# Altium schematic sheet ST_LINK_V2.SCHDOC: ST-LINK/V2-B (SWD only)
size A4; Date: Not used; ApprovedBy: Not used; CheckedBy: Not used; Author: Not used; CompanyName: STMicroelectronics; DrawnBy: Not used; Engineer: Not used; Organization: Not used; Address1: Not used; Address2: Not used; Address3: Not used; Address4: Not used; Revision: Not used; SheetNumber: 8; SheetTotal: 8
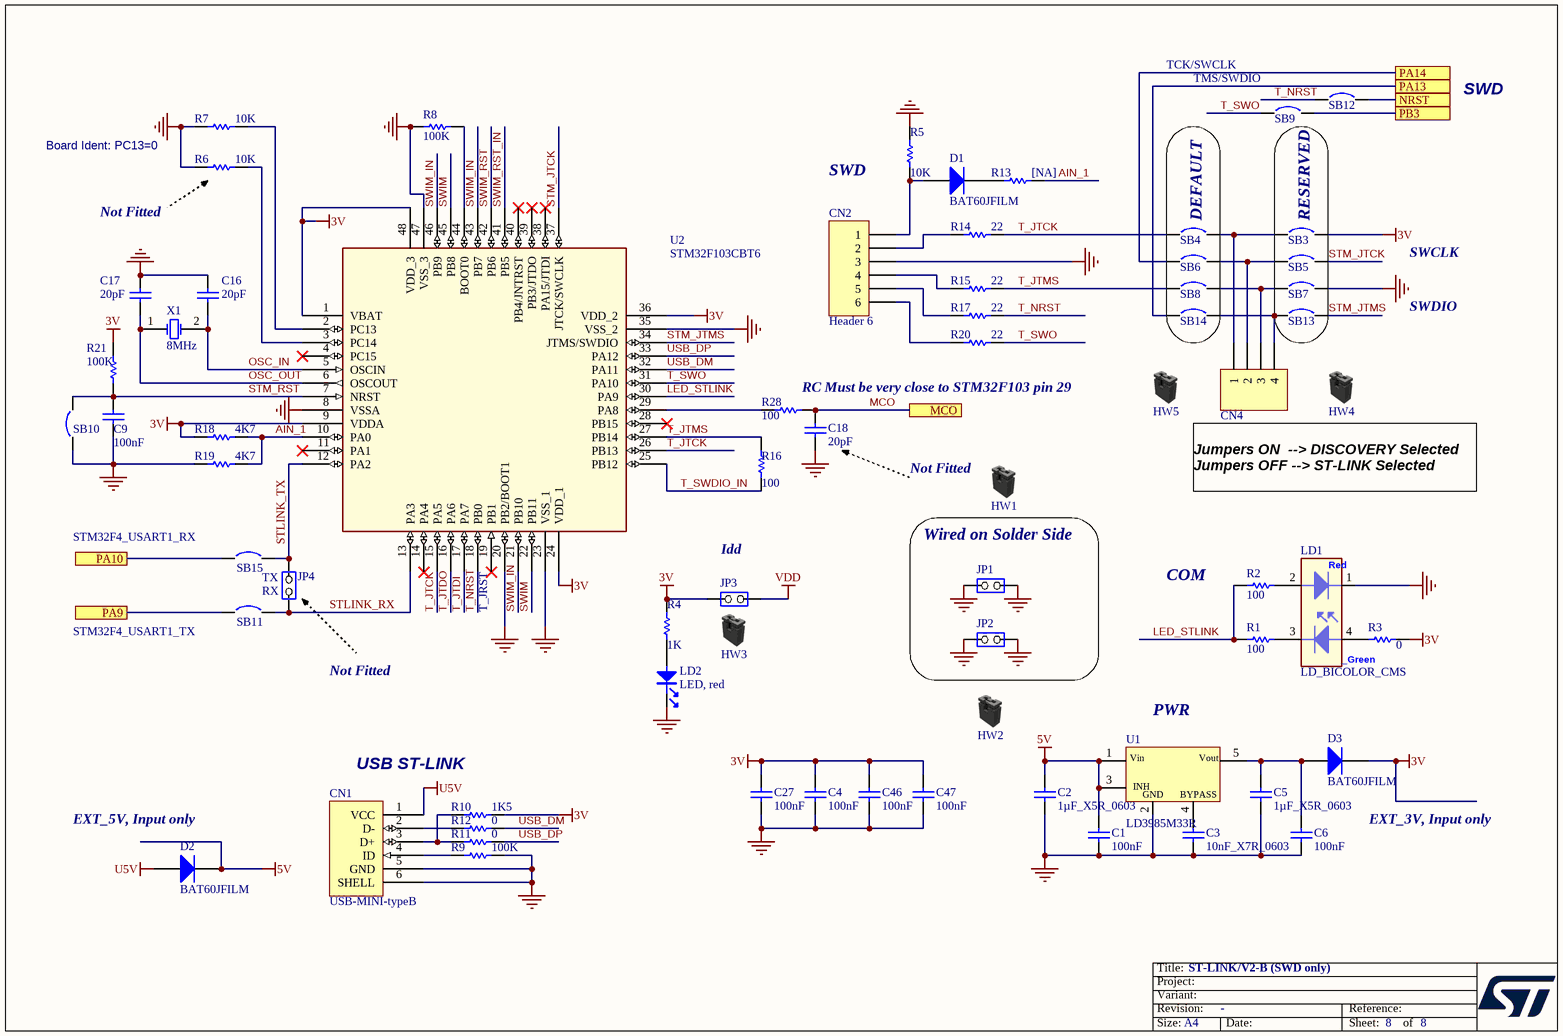
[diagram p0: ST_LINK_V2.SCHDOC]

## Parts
C1  100nF  [0402C]
C2  1µF_X5R_0603  [0603C]
C3  10nF_X7R_0603  [0603C]
C4  100nF  [0402C]
C5  1µF_X5R_0603  [0603C]
C6  100nF  [0402C]
C9  100nF  [0402C]
C16  20pF  [0402C]
C17  20pF  [0402C]
C18  20pF  [0402C]
C27  100nF  [0402C]
C46  100nF  [0402C]
C47  100nF  [0402C]
CN1  USB-MINI-typeB  [USB-MINI-B-SMD]
CN2  Header 6  [HDR1X6]
CN4  Header 4  [Header 4]  (value not drawn)
D1  BAT60JFILM  [SOD323/A]
D2  BAT60JFILM  [SOD323/A]
D3  BAT60JFILM  [SOD323/A]
HW1  Shunt Black 2.54mm  (value not drawn)  (mechanical)
HW2  Shunt Black 2.54mm  (value not drawn)  (mechanical)
HW3  Shunt Black 2.54mm  (value not drawn)  (mechanical)
HW4  Shunt Black 2.54mm  (value not drawn)  (mechanical)
HW5  Shunt Black 2.54mm  (value not drawn)  (mechanical)
JP1  (no value)  [SIP2/2.54]
JP2  (no value)  [SIP2/2.54]
JP3  (no value)  [SIP2/2.54]
JP4  JP2  [SIP2/2.54]  (value not drawn)
LD1  LD_BICOLOR_CMS  [HSMF-A201]
LD2  LED, red  [0603D]
R1  100  [0402R]
R2  100  [0402R]
R3  0  [0402R]
R4  1K  [0402R]
R5  10K  [0402R]
R6  10K  [0402R]
R7  10K  [0402R]
R8  100K  [0402R]
R9  100K  [0402R]
R10  1K5  [0402R]
R11  0  [0402R]
R12  0  [0402R]
R13  [NA]  [0402R]
R14  22  [0402R]
R15  22  [0402R]
R16  100  [0402R]
R17  22  [0402R]
R18  4K7  [0402R]
R19  4K7  [0402R]
R20  22  [0402R]
R21  100K  [0402R]
R28  100  [0402R]
SB3  Circuit Breaker  [JP2_SMD]  (value not drawn)
SB4  Circuit Breaker  [JP2_SMD]  (value not drawn)
SB5  Circuit Breaker  [JP2_SMD]  (value not drawn)
SB6  Circuit Breaker  [JP2_SMD]  (value not drawn)
SB7  Circuit Breaker  [JP2_SMD]  (value not drawn)
SB8  Circuit Breaker  [JP2_SMD]  (value not drawn)
SB9  Circuit Breaker  [JP2_SMD]  (value not drawn)
SB10  Circuit Breaker  [JP2_SMD]  (value not drawn)
SB11  Circuit Breaker  [JP2_SMD]  (value not drawn)
SB12  Circuit Breaker  [JP2_SMD]  (value not drawn)
SB13  Circuit Breaker  [JP2_SMD]  (value not drawn)
SB14  Circuit Breaker  [JP2_SMD]  (value not drawn)
SB15  Circuit Breaker  [JP2_SMD]  (value not drawn)
U1  LD3985M33R  [SOT-23-5L]
U2  STM32F103CBT6  [QFP48 7x7]
X1  8MHz  [XTAL1]

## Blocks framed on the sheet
DEFAULT: SB4 SB6 SB8 SB14
RESERVED: SB3 SB5 SB7 SB13
Wired on Solder Side: JP1 JP2

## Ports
MCO, NRST, PA9, PA10, PA13, PA14, PB3

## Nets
3V: C4.2 C27.2 C46.2 C47.2 D3.2(K) JP3.1(COMMON) R3.2 R4.2 R10.2 R18.1 R21.2 SB3.2 U2.1(VBAT) U2.9(VDDA) U2.24(VDD_1) U2.36(VDD_2) U2.48(VDD_3)
5V: C1.2 C2.2 D2.2(K) U1.1(Vin) U1.3(CE)
GND: C1.1 C2.1 C3.1 C4.1 C5.2 C6.1 C9.1 C16.2 C17.2 C18.1 C27.1 C46.1 C47.1 CN1.5(GND) CN1.6(SHELL) CN2.3 JP1.1(COMMON) JP1.2(NO) JP2.1(COMMON) JP2.2(NO) LD1.1 LD2.2 R5.2 R6.1 R7.1 R8.1 R9.2 R19.1 SB7.2 SB10.1 U1.2(GND) U2.8(VSSA) U2.20(PB2/BOOT1) U2.23(VSS_1) U2.35(VSS_2) U2.47(VSS_3)
U5V: CN1.1(VCC) D2.1(A)
VDD: JP3.2(NO)
AIN_1: R13.2 R18.2 R19.2 U2.10(PA0)
LED_STLINK: R1.1 R2.1 U2.30(PA9)
MCO: C18.2 R28.2 ; port MCO
NRST: SB12.2 ; port NRST
OSC_IN: C16.1 U2.5(OSCIN) X1.2(OSC2)
OSC_OUT: C17.1 U2.6(OSCOUT) X1.1(OSC1)
PA9: SB11.1 ; port PA9
PA10: SB15.1 ; port PA10
PA13: SB14.1 ; port PA13
PA14: SB6.1 ; port PA14
PB3: SB9.2 ; port PB3
STLINK_RX: JP4.1(COMMON) SB11.2 U2.13(PA3)
STLINK_TX: JP4.2(NO) SB15.2 U2.12(PA2)
STM_JTCK: SB5.2 U2.37(JTCK/SWCLK)
STM_JTMS: SB13.2 U2.34(JTMS/SWDIO)
STM_RST: C9.2 R21.1 SB10.2 U2.7(NRST)
SWIM: U2.22(PB11) U2.45(PB8)
SWIM_IN: U2.21(PB10) U2.43(PB7) U2.46(PB9)
SWIM_RST: U2.42(PB6)
SWIM_RST_IN: U2.41(PB5)
T_JTCK: R14.2 SB4.1 U2.15(PA5) U2.26(PB13)
T_JTDI: U2.17(PA7)
T_JTDO: U2.16(PA6)
T_JTMS: R15.2 R16.2 SB8.1 U2.27(PB14)
T_NRST: R17.2 SB12.1 U2.18(PB0)
T_SWDIO_IN: R16.1 U2.25(PB12)
T_SWO: R20.2 SB9.1 U2.31(PA10)
USB_DM: R12.2 U2.32(PA11)
USB_DP: R11.2 U2.33(PA12)
NetC3_2: C3.2 U1.4(BYPASS)
NetC5_1: C5.1 C6.2 D3.1(A) U1.5(Vout)
NetCN1_2: CN1.2(D-) R12.1
NetCN1_3: CN1.3(D+) R10.1 R11.1
NetCN1_4: CN1.4(ID) R9.1
NetCN2_1: CN2.1 D1.1(A) R5.1
NetCN2_2: CN2.2 R14.1
NetCN2_4: CN2.4 R15.1
NetCN2_5: CN2.5 R17.1
NetCN2_6: CN2.6 R20.1
NetCN4_1: CN4.1 SB3.1 SB4.2
NetCN4_2: CN4.2 SB5.1 SB6.2
NetCN4_3: CN4.3 SB7.1 SB8.2
NetCN4_4: CN4.4 SB13.1 SB14.2
NetD1_2: D1.2(K) R13.1
NetLD1_2: LD1.2 R2.2
NetLD1_3: LD1.3 R1.2
NetLD1_4: LD1.4 R3.1
NetLD2_1: LD2.1 R4.1
NetR6_2: R6.2 U2.3(PC14)
NetR7_2: R7.2 U2.2(PC13)
NetR8_2: R8.2 U2.44(BOOT0)
NetR28_1: R28.1 U2.29(PA8)

Not connected (* = marked no-connect by the designer): U2 4(PC15)* 11(PA1)* 14(PA4)* 19(PB1)* 28(PB15)* 38(PA15/JTDI)* 39(PB3/JTDO)* 40(PB4/JNTRST)*

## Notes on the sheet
- TCK/SWCLK
- (near SB9) TMS/SWDIO
- SWD
- Board Ident: PC13=0
- Not Fitted
- SWCLK
- SWDIO
- (near R28) RC Must be very close to STM32F103 pin 29
- (near HW1) Not Fitted
- Jumpers ON  --> DISCOVERY Selected
  Jumpers OFF --> ST-LINK Selected
- STM32F4_USART1_RX
- TX
- Idd
- COM
- STM32F4_USART1_TX
- RX
- (near U2) T_JRST
- (near U1) PWR
- USB ST-LINK
- (near D2) EXT_5V, Input only
- EXT_3V, Input only

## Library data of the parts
C1 C4 C6 C9 C27 C46 C47 = Capacitor_ST: Capacitor 0402 / 0603 / 0805
C2 C5 = CAP SMD 0603  X5R 1µF 25V 10%: 0603  X5R 1µF; Rated voltage: 25V; Tolerance: 10%
C3 = CAP SMD 0603  X7R 10000PF 50V 10%: 0603  X7R 10NF; Order code RS: 2040779; Rated voltage: 50V; Tolerance: 10%
C16 C17 = Capacitor_ST: Capacitor 0402 / 0603 / 0805; Value: 100nF
C18 = Capacitor_ST: Capacitor 0402 / 0603 / 0805; Value: 100nF; Fitted: NO
CN1 = USB-MINI-typeB connector: Manuf_Part_1: 5075BMR-05-SM; Manuf_Part_2: 218205M1110T; Manuf_2: lyconn
CN2 = Header 6: Header, 6-Pin
CN4 = Header 4: Header, 4-Pin
D1-D3 = BAT60JFILM: Manuf_1: STM; Provided: ST; ECCN_US/EU: EAR99/NEC
JP1-JP3 = JP2
JP4 = JP2: Fitted: NO
LD1 = LD_BICOLOR_CMS: Bicolor Led; Manuf_Part_1: HSMF-A201-A00J1; Manuf_1: Avago Technologies; Manuf_2: everluck; Manuf_Part_2: LE-RGW35280; Ref St: xxxxxx
LD2 = LED_red: LED, red, 0603; Manuf_1: everlight; Manuf_Part_1: 19-213-R6C-AP1Q2B/3T
R1-R4 R8-R12 R14-R21 R28 = Resistor_ST: Resistor 0402 / 0603 / 0805; Value: 10K
R5 R7 = Resistor_ST: Resistor 0402 / 0603 / 0805
R6 = Resistor_ST: Resistor 0402 / 0603 / 0805; Fitted: NO
R13 = Resistor_ST: Resistor 0402 / 0603 / 0805; Value: 10K; Fitted: NO
SB3 SB5 SB7 SB11-SB13 SB15 = Circuit Breaker: Solder: YES
SB4 SB6 SB8-SB10 SB14 = Circuit Breaker: Solder: NO
U1 = LD3985M33R: Ultra low drop-low noise BiCMOS voltage, regulators low ESR capacitors compatible; Manuf_1: STM; Provided: ST; Ref St: 9176161; ECCN_US/EU: EAR99/NEC
U2 = STM32F103CBT6: Medium-density performance line ARM-based 32-bit MCU with 128KB Flash; Manuf_1: STM; Ref St: xxxxxxxx; Provided: ST; ECCN_US/EU: 3A991A2/NEC
X1 = XTAL: Crystal Oscillator,8Mhz,20PF,20PPM,-10-70 degree,DIP,HC-49S; Manuf_Part_1: 9SL8000020AFXHF0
